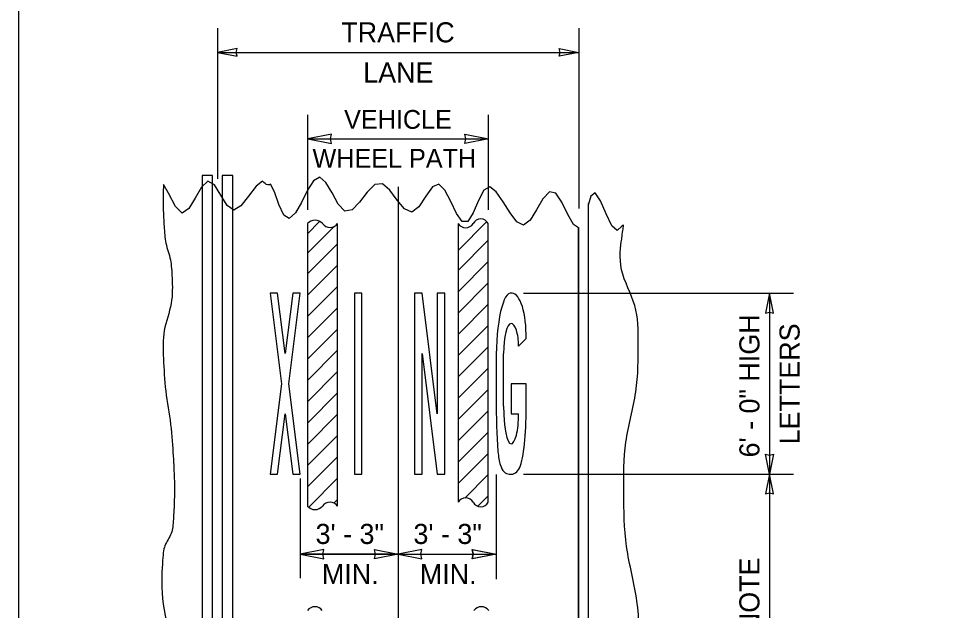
# Model space of a CAD drawing. Extents: x 99862 to 103151, y 100000 to 105076.
# Drawn here: x 99862 to 100601, y 100517 to 100988 of the extents above; entities that cross this region are included whole.
import ezdxf

# ---------------------------------------------------------------- set-up
doc = ezdxf.new("R2010")
doc.units = 0
for name, color, linetype in [('Level 1', 7, 'Continuous'), ('Level 15', 7, 'Continuous'), ('Level 2', 7, 'Continuous'), ('Level 20', 7, 'Continuous'), ('Level 6', 7, 'Continuous'), ('Level 7', 7, 'Continuous'), ('Level 8', 7, 'Continuous')]:
    doc.layers.add(name, color=color, linetype=linetype)

msp = doc.modelspace()

# ---------------------------------------------------------------- linework, layer by layer
at = {"layer": 'Level 1'}
msp.add_lwpolyline([(99862, 99999.5), (103151, 99999.5), (103151, 102075.5), (99862, 102075.5)], close=True, dxfattribs=at)
at = {"layer": 'Level 15'}
for p, q in [((100020.42, 100980.46), (100020.42, 100860.46)), ((100308.42, 100980.46), (100308.42, 100837.01)), ((100020.42, 100961.26), (100308.42, 100961.26)), ((100092.42, 100835.74), (100092.42, 100911.59)), ((100236.42, 100835.74), (100236.42, 100911.59)), ((100092.42, 100892.39), (100236.42, 100892.39)), ((100164.42, 100854.19), (100164.42, 100505.89)), ((100092.2, 100824.86), (100092.2, 100599.87)), ((100116.2, 100599.87), (100116.2, 100824.86)), ((100264.36, 100769.37), (100479.48, 100769.37)), ((100460.28, 100769.37), (100460.28, 100625.37)), ((100086.42, 100621.87), (100086.42, 100542.47)), ((100242.42, 100625), (100242.42, 100541.67)), ((100264.36, 100625.37), (100479.48, 100625.37)), ((100460.28, 100625.37), (100460.28, 100385.87)), ((100086.42, 100561.67), (100164.42, 100561.67)), ((100164.42, 100561.67), (100086.47, 100561.67)), ((100164.42, 100561.67), (100242.42, 100561.67)), ((100164.42, 100561.67), (100242.32, 100561.67))]:
    msp.add_line(p, q, dxfattribs=at)
for points in [[(100020.42, 100961.26), (100036.14, 100958.18), (100035.42, 100961.26), (100036.14, 100964.34)], [(100308.42, 100961.26), (100292.69, 100958.18), (100293.42, 100961.26), (100292.69, 100964.34)], [(100092.42, 100892.39), (100111.29, 100888.69), (100110.42, 100892.39), (100111.29, 100896.09)], [(100236.42, 100892.39), (100217.55, 100888.69), (100218.42, 100892.39), (100217.55, 100896.09)], [(100460.28, 100769.37), (100457.2, 100753.64), (100460.28, 100754.37), (100463.36, 100753.64)], [(100460.28, 100625.37), (100457.2, 100641.09), (100460.28, 100640.36), (100463.36, 100641.09)], [(100460.28, 100625.37), (100457.2, 100609.64), (100460.28, 100610.37), (100463.36, 100609.64)], [(100086.42, 100561.67), (100105.29, 100557.96), (100104.42, 100561.67), (100105.29, 100565.37)], [(100086.47, 100561.67), (100105.34, 100557.96), (100104.47, 100561.67), (100105.34, 100565.37)], [(100164.42, 100561.67), (100145.55, 100557.96), (100146.42, 100561.67), (100145.55, 100565.37)], [(100164.42, 100561.67), (100183.29, 100557.96), (100182.42, 100561.67), (100183.29, 100565.37)], [(100242.32, 100561.67), (100223.45, 100557.96), (100224.32, 100561.67), (100223.45, 100565.37)], [(100242.42, 100561.67), (100223.55, 100557.96), (100224.42, 100561.67), (100223.55, 100565.37)]]:
    msp.add_lwpolyline(points, close=True, dxfattribs=at)
for points in [[(100212.2, 100824.86), (100212.2, 100602.87)], [(100236.2, 100602.87), (100236.2, 100824.86)]]:
    msp.add_lwpolyline(points, dxfattribs=at)
for centre, radius, start, end in [((100230.2, 100821.95), 6.67, 25.9249, 154.0751), ((100098.2, 100819.69), 7.92, 40.75287, 139.24713), ((100098.2, 100819.69), 7.92, 40.75287, 139.24713), ((100110.2, 100829.36), 7.5, 216.8699, 323.1301), ((100110.2, 100829.36), 7.5, 216.8699, 323.1301), ((100218.2, 100828.78), 7.16, 213.11414, 326.88586), ((100218.24, 100599.53), 6.9, 28.88658, 151.11342), ((100098.16, 100604.78), 7.72, 219.50691, 320.49309), ((100110.16, 100595.33), 7.55, 36.89097, 143.10903), ((100230.24, 100606.18), 6.82, 209.09347, 330.90653), ((100098.1, 100512.43), 7.29, 36.05144, 143.94856), ((100230.74, 100512.43), 7.29, 36.05144, 143.94856)]:
    msp.add_arc(centre, radius, start, end, dxfattribs=at)
at = {"layer": 'Level 2'}
for points in [[(100008.2, 100863.17), (100008.2, 100098.04)], [(100016.64, 100863.17), (100008.2, 100863.17)], [(100008.2, 100863.17), (100008.2, 100095.42)], [(100016.64, 100114.68), (100016.64, 100863.17)], [(100016.64, 100095.42), (100016.64, 100863.17)], [(100024.2, 100863.17), (100024.2, 100095.42)], [(100032.64, 100863.17), (100024.2, 100863.17)], [(100024.2, 100863.17), (100024.2, 100095.42)], [(100032.64, 100095.42), (100032.64, 100863.17)], [(100032.64, 100095.42), (100032.64, 100863.17)]]:
    msp.add_lwpolyline(points, dxfattribs=at)
at = {"layer": 'Level 6'}
for p, q in [((100092.2, 100816.84), (100101.89, 100826.53)), ((100092.2, 100801.39), (100113.17, 100822.35)), ((100212.38, 100803.8), (100234.84, 100826.26)), ((100092.2, 100784.78), (100116.2, 100808.78)), ((100212.2, 100787.56), (100236.2, 100811.56)), ((100092.2, 100767.81), (100116.2, 100791.81)), ((100212.2, 100770.59), (100236.2, 100794.59)), ((100212.2, 100753.62), (100236.2, 100777.62)), ((100092.2, 100750.84), (100116.2, 100774.84)), ((100092.2, 100733.87), (100116.2, 100757.87)), ((100212.2, 100736.65), (100236.2, 100760.65)), ((100092.2, 100716.9), (100116.2, 100740.9)), ((100212.2, 100719.68), (100236.2, 100743.68)), ((100212.2, 100702.7), (100236.2, 100726.7)), ((100092.2, 100699.93), (100116.2, 100723.93)), ((100212.2, 100685.73), (100236.2, 100709.73)), ((100092.2, 100682.96), (100116.2, 100706.96)), ((100092.2, 100665.99), (100116.2, 100689.99)), ((100212.2, 100668.76), (100236.2, 100692.76)), ((100092.2, 100649.02), (100116.2, 100673.02)), ((100212.2, 100651.79), (100236.2, 100675.79)), ((100212.2, 100634.82), (100236.2, 100658.82)), ((100092.2, 100632.05), (100116.2, 100656.05)), ((100092.2, 100615.08), (100116.2, 100639.08)), ((100212.2, 100617.85), (100236.2, 100641.85)), ((100093.15, 100599.06), (100116.2, 100622.11)), ((100217.61, 100606.29), (100236.2, 100624.88)), ((100228.04, 100599.75), (100236.2, 100607.91)), ((100113.21, 100602.15), (100116.2, 100605.14))]:
    msp.add_line(p, q, dxfattribs=at)
for points in [[(100008.2, 100854.23), (100008.2, 100118.21)], [(100016.64, 100114.5), (100016.64, 100856.71)], [(100024.2, 100846.45), (100024.2, 100125.32)], [(100032.64, 100132.26), (100032.64, 100836.64)], [(100315.74, 100840.91), (100315.74, 100118.69)], [(100308.2, 100821.76), (100308.2, 100135.8)]]:
    msp.add_lwpolyline(points, dxfattribs=at)
at = {"layer": 'Level 7'}
for points in [[(100056.24, 100858.79), (100051.36, 100854.61), (100045.19, 100846.61), (100039.05, 100839.08), (100033.41, 100835.6), (100028.26, 100839.26), (100023.12, 100847.66), (100017.99, 100855.77), (100012.88, 100858.57), (100007.77, 100853.81), (100002.66, 100845.1), (99997.56, 100836.8), (99992.45, 100833.28), (99987.01, 100838.48), (99981.36, 100849.09), (99977.58, 100856.12)], [(100308.2, 100821.61), (100304.07, 100824.1), (100299.54, 100832.19), (100294.83, 100841.83), (100289.95, 100849.13), (100284.91, 100850.26), (100279.83, 100844.7), (100274.71, 100835.94), (100269.56, 100827.71), (100264.38, 100823.72), (100259.06, 100826.32), (100253.56, 100833.42), (100248.03, 100842.26), (100242.61, 100850.09), (100237.44, 100854.14), (100232.69, 100851.57), (100228.35, 100843.22), (100224.17, 100833.39), (100219.93, 100826.46), (100215.46, 100826.47), (100210.94, 100832.95), (100206.37, 100842.42), (100201.7, 100851.4), (100196.87, 100856.38), (100191.84, 100854.24), (100186.53, 100846.63), (100181, 100838.26), (100175.29, 100833.89), (100169.46, 100836.57), (100163.61, 100843.59), (100157.73, 100851.44), (100151.83, 100856.63), (100145.87, 100855.93), (100139.77, 100849.92), (100133.65, 100842.06), (100127.69, 100835.88), (100122.03, 100834.92), (100116.77, 100840.47), (100111.78, 100849.31), (100106.91, 100857.68), (100102.03, 100861.81), (100097.1, 100859.09), (100092.21, 100851.41), (100087.35, 100841.82), (100082.52, 100833.35), (100077.72, 100829.04), (100073.25, 100831.67), (100069.46, 100840.01), (100065.86, 100850.08), (100062.75, 100856.22)], [(100343.91, 100823.55), (100342.59, 100822.81), (100339.05, 100819.35), (100334.8, 100823.04), (100330.19, 100832.64), (100325.61, 100843.09), (100321.47, 100849.31), (100318.07, 100846.86), (100315.74, 100839.67)], [(100315.74, 100839.67), (100315.74, 100119.06)], [(100308.2, 100135.66), (100308.2, 100821.61)]]:
    msp.add_lwpolyline(points, dxfattribs=at)
for points in [[(100062.75, 100856.22), (100062.32, 100855.96), (100061.88, 100855.81), (100061.44, 100855.77), (100059.84, 100855.64), (100058.09, 100856.78), (100056.24, 100858.79)], [(99977.58, 100856.12), (99976.96, 100850.06), (99977.12, 100836.24), (99977.94, 100822.61), (99978.74, 100809.25), (99983.67, 100796.09), (99984.24, 100782.7), (99985.17, 100761.18), (99976.49, 100739.65), (99977.42, 100718.11), (99978.56, 100691.51), (99983.8, 100664.9), (99985.29, 100638.29), (99986.22, 100621.74), (99986.25, 100604.96), (99985.29, 100588.41), (99984.69, 100577.93), (99977.52, 100568.43), (99976.89, 100557.95), (99974.72, 100521.75), (99987.31, 100485.45), (99986.87, 100449.25), (99986.44, 100413.88), (99975.82, 100378.42), (99975.84, 100343.17), (99975.85, 100316.89), (99993.14, 100291.43), (99992.64, 100265.45), (99992.11, 100237.52), (99976.72, 100209.88), (99976.89, 100181.43), (99977.05, 100154.42), (99980.94, 100127.35), (99980.3, 100130.3), (99980.18, 100124.85), (99980.02, 100119.78), (99979.85, 100114.99)], [(100351.18, 100182.7), (100348.38, 100196.33), (100342.68, 100209.9), (100342.07, 100223.44), (100341.17, 100243.48), (100356.72, 100262.97), (100356.77, 100283.31), (100356.86, 100314.73), (100344.39, 100346.29), (100345.22, 100377.83), (100346.13, 100412.14), (100356.85, 100446.39), (100356.77, 100480.76), (100356.67, 100524.16), (100344.48, 100567.58), (100344.17, 100610.99), (100343.88, 100650.9), (100355.76, 100690.82), (100355.72, 100730.72), (100355.7, 100759.59), (100339.04, 100788.11), (100343.12, 100816.84), (100343.59, 100820.16), (100344.06, 100823.49), (100343.91, 100823.55)]]:
    msp.add_open_spline(points, degree=3, dxfattribs=at)
at = {"layer": 'Level 8'}
for p, q in [((100255.16, 100769.37), (100253.57, 100769.37)), ((100260.39, 100727.37), (100266.36, 100733.37)), ((100248.44, 100679.37), (100248.44, 100721.37)), ((100242.46, 100709.37), (100242.46, 100685.37)), ((100266.37, 100697.36), (100254.42, 100697.36)), ((100254.42, 100697.36), (100254.42, 100673.36)), ((100266.37, 100685.36), (100266.37, 100697.36)), ((100254.42, 100673.36), (100260.39, 100673.36)), ((100252.8, 100625.37), (100254.42, 100625.37)), ((100254.42, 100625.37), (100255.75, 100625.37))]:
    msp.add_line(p, q, dxfattribs=at)
for points in [[(100071.42, 100697.37), (100062.42, 100625.37), (100068.42, 100625.37), (100074.42, 100673.37), (100080.42, 100625.37), (100086.42, 100625.37), (100077.42, 100697.37), (100086.42, 100769.37), (100080.42, 100769.37), (100074.42, 100721.37), (100068.42, 100769.37), (100062.42, 100769.37)], [(100129.56, 100625.37), (100135.56, 100625.37), (100135.56, 100769.37), (100129.56, 100769.37)], [(100183.56, 100721.37), (100195.56, 100625.37), (100201.56, 100625.37), (100201.56, 100769.37), (100195.56, 100769.37), (100195.56, 100673.37), (100183.56, 100769.37), (100177.56, 100769.37), (100177.56, 100625.37), (100183.56, 100625.37)]]:
    msp.add_lwpolyline(points, close=True, dxfattribs=at)
for points in [[(100062.42, 100769.37), (100071.42, 100697.37), (100062.42, 100625.37), (100068.42, 100625.37), (100074.42, 100673.37), (100080.42, 100625.37), (100086.42, 100625.37), (100077.42, 100697.37), (100086.42, 100769.37), (100080.42, 100769.37), (100074.42, 100721.37), (100068.42, 100769.37), (100062.42, 100769.37)], [(100129.56, 100769.37), (100129.56, 100625.37), (100135.56, 100625.37), (100135.56, 100769.37), (100129.56, 100769.37)], [(100183.56, 100625.37), (100183.56, 100721.37), (100195.56, 100625.37), (100201.56, 100625.37), (100201.56, 100769.37), (100195.56, 100769.37), (100195.56, 100673.37), (100183.56, 100769.37), (100177.56, 100769.37), (100177.56, 100625.37), (100183.56, 100625.37)], [(100255.16, 100769.37), (100253.57, 100769.37)], [(100260.39, 100727.37), (100266.36, 100733.37)], [(100248.44, 100679.37), (100248.44, 100721.37)], [(100242.46, 100709.37), (100242.46, 100685.37)], [(100266.37, 100685.36), (100266.37, 100697.36), (100254.42, 100697.36), (100254.42, 100673.36), (100260.39, 100673.36)], [(100252.8, 100625.37), (100254.42, 100625.37), (100255.75, 100625.37)]]:
    msp.add_lwpolyline(points, dxfattribs=at)
for centre, major_axis, ratio, start_param, end_param in [((100254.61, 100711.78), (0.56, -57.63), 0.211348, 3.18149, 4.752287), ((100254.61, 100711.78), (0.56, -57.63), 0.211348, 3.18149, 4.752287), ((100254.39, 100733.56), (-0.79, -35.8), 0.3343, 1.572771, 3.143568), ((100254.39, 100733.56), (-0.79, -35.8), 0.3343, 1.572771, 3.143568), ((100254.41, 100721.37), (0, -24), 0.248926, 3.141593, 4.712389), ((100254.41, 100721.37), (0, -24), 0.248926, 3.141593, 4.712389), ((100254.41, 100727.37), (0, -18), 0.331902, 1.570796, 3.141593), ((100254.41, 100727.37), (0, -18), 0.331902, 1.570796, 3.141593), ((100273.97, 100713.87), (-6.99, -141.72), 0.216751, 4.925572, 5.243713), ((100273.97, 100713.87), (-6.99, -141.72), 0.216751, 4.925572, 5.243713), ((100256.68, 100684.44), (0.87, -59.59), 0.16287, 0.554923, 1.58392), ((100256.68, 100684.44), (0.87, -59.59), 0.16287, 0.554923, 1.58392), ((100254.41, 100679.37), (0, -30), 0.199141, 4.712389, 6.283185), ((100254.41, 100679.37), (0, -30), 0.199141, 4.712389, 6.283185), ((100254.41, 100673.36), (0, -23.99), 0.249371, 6.283185, 7.853982), ((100254.41, 100673.36), (0, -23.99), 0.249371, 6.283185, 7.853982), ((100250.97, 100661.4), (-2.26, -32.26), 0.216768, 5.320456, 5.812321), ((100250.97, 100661.4), (-2.26, -32.26), 0.216768, 5.320456, 5.812321), ((100266.92, 100698.38), (-15.35, -72.92), 0.244228, 5.877049, 6.350097), ((100266.92, 100698.38), (-15.35, -72.92), 0.244228, 5.877049, 6.350097), ((100161.02, 100856.31), (95.55, -230.66), 0.169025, 6.262693, 6.489624), ((100161.02, 100856.31), (95.55, -230.66), 0.169025, 6.262693, 6.489624)]:
    msp.add_ellipse(centre, major_axis=major_axis, ratio=ratio, start_param=start_param, end_param=end_param, dxfattribs=at)

# ---------------------------------------------------------------- texts
at = {"layer": 'Level 20'}
for s, height, rotation, p in [('TRAFFIC', 16, 360, (100119.15, 100969.26)), ('LANE', 16, 360, (100136.64, 100937.26)), ('VEHICLE', 15, 360, (100121.4, 100900.39)), ('WHEEL PATH', 15, 360, (100096.21, 100869.39)), ('6\' - 0" HIGH', 16, 90, (100452.28, 100638.61)), ('LETTERS', 16, 90, (100484.28, 100649.06)), ('3\' - 3"', 16, 360, (100098.66, 100569.67)), ('3\' - 3"', 16, 360, (100176.63, 100569.67)), ('SEE NOTE', 16, 90, (100452.28, 100450.68)), ('MIN.', 16, 360, (100103.72, 100537.67)), ('MIN.', 16, 360, (100181.7, 100537.67))]:
    msp.add_text(s, height=height, rotation=rotation, dxfattribs=at).set_placement(p)

doc.saveas('drawing.dxf')
